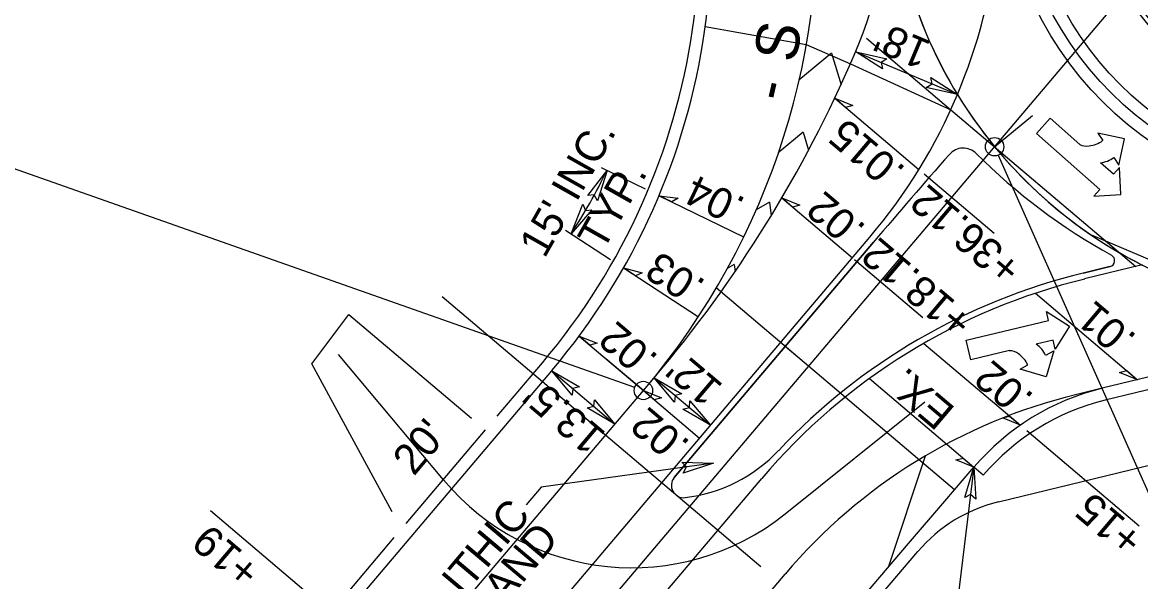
# Model space of a CAD drawing. Extents: x 1761082 to 1764358, y 421907 to 425434.
# Drawn here: x 1762006.6 to 1762189, y 422867.6 to 422958.8 of the extents above; entities that cross this region are included whole.
import ezdxf

# ---------------------------------------------------------------- set-up
doc = ezdxf.new("R2010")
doc.units = 0
for name, color, linetype in [('MARK DUAL LEFT TURN ARROWS CELL', 7, 'Continuous'), ('MARK HOOKS CENTER STRAIGHT LEFT TURN ARROW CELL', 7, 'Continuous'), ('MARK HOOKS STRAIGHT RIGHT TURN ARROW CELL', 7, 'Continuous'), ('MARK LEFT TURN ARROW CELL', 7, 'Continuous'), ('MARK ONLY WORD SYMBOL CELL', 7, 'Continuous'), ('MARK STRAIGHT RIGHT ARROW CELL', 7, 'Continuous'), ('MARK UTURN ARROW CELL', 7, 'Continuous'), ('Prop Conc Driveway', 7, 'Continuous'), ('Prop Horizontal Alignment Tick Large', 7, 'Continuous'), ('Prop Mkg 3ft Min Skp 3ft Wide White', 7, 'Continuous'), ('Prop Mkg 3ft Min Skp 9ft White', 7, 'Continuous'), ('Prop Mkg 3ft Min Skp 9ft Wide White', 7, 'Continuous'), ('Prop Mkg Min Skp 6ft Yellow', 7, 'Continuous'), ('Prop Mkg Skp Wht', 7, 'Continuous'), ('Prop Mkg Solid White Diagonals', 7, 'Continuous'), ('Prop Mkg Solid White Gore Line', 7, 'Continuous'), ('Prop Mkg Solid White Multiple Diagonals V8i', 7, 'Continuous'), ('Prop Mkg Solid Yel Skip LT', 7, 'Continuous'), ('Prop Mkg Solid Yel Skip RT', 7, 'Continuous'), ('Prop Mkg Solid Yellow Diagonals', 7, 'Continuous'), ('Prop Mkg Solid Yellow Edge Line', 7, 'Continuous'), ('Prop Mkg Solid Yellow Lane Line', 7, 'Continuous'), ('Prop Mkr CR 80ft Spc', 7, 'Continuous'), ('Prop Mkr Yel 80ft Spc', 7, 'Continuous'), ('Scratch_Level_0', 7, 'Continuous'), ('Scratch_Level_1', 7, 'Continuous'), ('Scratch_Level_5', 7, 'Continuous'), ('Text', 7, 'Continuous')]:
    doc.layers.add(name, color=color, linetype=linetype)

msp = doc.modelspace()

# ---------------------------------------------------------------- linework, layer by layer
at = {"layer": 'MARK DUAL LEFT TURN ARROWS CELL'}
msp.add_line((1762165.16, 422938.49), (1762188.21, 422918.96), dxfattribs=at)
at = {"layer": 'MARK HOOKS CENTER STRAIGHT LEFT TURN ARROW CELL'}
msp.add_line((1762134.83, 422902.69), (1762131.02, 422905.92), dxfattribs=at)
at = {"layer": 'MARK LEFT TURN ARROW CELL'}
for p, q in [((1762241.31, 422911.3), (1762183.21, 422897.16)), ((1762084.06, 422894.58), (1762091.42, 422903.27)), ((1762163.32, 422884.94), (1762161.8, 422886.24)), ((1762056.89, 422862.51), (1762067.26, 422874.75))]:
    msp.add_line(p, q, dxfattribs=at)
for centre, radius, start, end in [((1762009.01, 422973.08), 108, 319.7301, 23.7856), ((1762192.2, 422860.24), 38, 103.6821, 139.4555)]:
    msp.add_arc(centre, radius, start, end, dxfattribs=at)
at = {"layer": 'MARK ONLY WORD SYMBOL CELL'}
msp.add_line((1762069.2, 422877.04), (1762082.12, 422892.3), dxfattribs=at)
at = {"layer": 'MARK STRAIGHT RIGHT ARROW CELL'}
msp.add_line((1761294.53, 421910.78), (1762672.97, 423537.92), dxfattribs=at)
msp.add_arc((1762016.33, 422976.3), 120, 319.7301, 48.9609, dxfattribs=at)
at = {"layer": 'MARK UTURN ARROW CELL'}
for points in [[(1762106.48, 422899.23), (1761972.71, 422946.36), (1761882.86, 422840.3)], [(1762165.77, 422937.12), (1762234.28, 422783.03), (1762150.66, 422684.32)]]:
    msp.add_lwpolyline(points, dxfattribs=at)
for centre in [(1762165.16, 422938.49), (1762165.16, 422938.49), (1762107.89, 422898.74)]:
    msp.add_circle(centre, 1.5, dxfattribs=at)
at = {"layer": 'Prop Conc Driveway'}
for p, q in [((1762053.82, 422903.11), (1762059.86, 422911.16)), ((1762059.86, 422911.16), (1762079.83, 422894.23)), ((1762066.91, 422878.97), (1762053.82, 422903.11))]:
    msp.add_line(p, q, dxfattribs=at)
at = {"layer": 'Prop Horizontal Alignment Tick Large'}
for p, q in [((1762165.16, 422938.49), (1762171.34, 422943.57)), ((1762107.89, 422898.74), (1762101.79, 422903.91))]:
    msp.add_line(p, q, dxfattribs=at)
at = {"layer": 'Prop Mkg 3ft Min Skp 3ft Wide White'}
msp.add_line((1761294.53, 421910.78), (1762672.97, 423537.92), dxfattribs=at)
for centre, radius, start, end in [((1762016.33, 422976.3), 120, 319.7301, 48.9609), ((1762223.1, 422986.12), 75, 149.3002, 219.4239), ((1762223.1, 422986.12), 75, 219.4239, 320.8368)]:
    msp.add_arc(centre, radius, start, end, dxfattribs=at)
at = {"layer": 'Prop Mkg 3ft Min Skp 9ft White'}
msp.add_circle((1762223.1, 422986.12), 55, dxfattribs=at)
at = {"layer": 'Prop Mkg 3ft Min Skp 9ft Wide White'}
msp.add_line((1762165.78, 422880.57), (1762244.15, 422899.64), dxfattribs=at)
msp.add_lwpolyline([(1762074.01, 422782.47), (1762075.07, 422783.67), (1762078.74, 422787.78), (1762082.33, 422791.8), (1762088.47, 422798.73), (1762093.54, 422804.54), (1762099.47, 422811.3), (1762102.88, 422815.18), (1762106.42, 422819.2), (1762109.92, 422823.18), (1762113.38, 422827.1), (1762116.8, 422830.99), (1762122.94, 422837.96), (1762127.73, 422843.46), (1762131.92, 422848.3), (1762136.29, 422853.34), (1762141.13, 422858.95), (1762152.67, 422872.49)], dxfattribs=at)
msp.add_arc((1762171.7, 422856.28), 25, 103.6821, 139.5617, dxfattribs=at)
at = {"layer": 'Prop Mkg Skp Wht'}
for p, q in [((1762240.84, 422913.25), (1762182.73, 422899.1)), ((1762058.44, 422861.25), (1762092.94, 422901.97))]:
    msp.add_line(p, q, dxfattribs=at)
msp.add_lwpolyline([(1762072.51, 422783.8), (1762073.58, 422785), (1762077.25, 422789.11), (1762080.84, 422793.13), (1762086.97, 422800.06), (1762092.04, 422805.85), (1762097.97, 422812.62), (1762101.38, 422816.5), (1762104.92, 422820.52), (1762108.42, 422824.5), (1762111.88, 422828.43), (1762115.3, 422832.31), (1762121.43, 422839.28), (1762126.22, 422844.77), (1762130.41, 422849.61), (1762134.78, 422854.65), (1762139.61, 422860.25), (1762145.2, 422866.81), (1762151.14, 422873.79), (1762157.03, 422880.67), (1762161.8, 422886.24)], dxfattribs=at)
for centre, radius, start, end in [((1762009.01, 422973.08), 110, 319.7301, 23.7856), ((1762192.2, 422860.24), 40, 103.6821, 139.4555)]:
    msp.add_arc(centre, radius, start, end, dxfattribs=at)
at = {"layer": 'Prop Mkg Solid White Diagonals'}
for p, q in [((1762145.43, 422922.94), (1762112.92, 422884.56)), ((1762179.62, 422917.9), (1762183.98, 422918.96))]:
    msp.add_line(p, q, dxfattribs=at)
for radius in [53, 43]:
    msp.add_circle((1762223.1, 422986.12), radius, dxfattribs=at)
for centre, radius, start, end in [((1762908.44, 422276.55), 1000, 138.64649, 139.7301), ((1762160.05, 422935.27), 3, 45.1345, 138.6465), ((1762232.71, 423008.27), 100, 225.1345, 241.0035), ((1762183.75, 422919.93), 1, 283.6821, 61.0035), ((1762203.51, 422819.76), 101, 103.6821, 136.7449), ((1762111.74, 422906.1), 25, 276.7589, 316.7449), ((1762114.45, 422883.26), 2, 139.7301, 276.7589)]:
    msp.add_arc(centre, radius, start, end, dxfattribs=at)
at = {"layer": 'Prop Mkg Solid White Gore Line'}
for radius in [43, 42.25]:
    msp.add_circle((1762223.1, 422986.12), radius, dxfattribs=at)
at = {"layer": 'Prop Mkg Solid White Multiple Diagonals V8i'}
for p, q in [((1762142.51, 422954), (1762159.1, 422947.01)), ((1762134.83, 422902.69), (1762119.76, 422915.46)), ((1762127.03, 422869.98), (1762075.06, 422914.01)), ((1762075.31, 422884.17), (1762058.19, 422904.63)), ((1761636.39, 422342), (1762107.89, 422898.74)), ((1762131, 422878.62), (1762153.81, 422896.89))]:
    msp.add_line(p, q, dxfattribs=at)
for radius in [57, 53]:
    msp.add_circle((1762223.1, 422986.12), radius, dxfattribs=at)
for centre, radius, start, end in [((1762076.16, 422981.94), 90, 337.1611, 1.6276), ((1762223.1, 422986.12), 75, 181.6276, 211.4287), ((1762105.99, 422909.83), 40, 219.9102, 308.6979)]:
    msp.add_arc(centre, radius, start, end, dxfattribs=at)
at = {"layer": 'Prop Mkg Solid Yel Skip RT'}
for p, q in [((1762142.51, 422954), (1762159.1, 422947.01)), ((1762100.98, 422935.12), (1762108.2, 422931.61)), ((1762153.67, 422934.07), (1762165.11, 422924.38)), ((1762095.2, 422924.88), (1762102.55, 422920.08)), ((1762142.33, 422920.09), (1762153.47, 422910.65)), ((1762092.94, 422901.97), (1762103.22, 422893.27)), ((1762109.66, 422900.81), (1762118.81, 422893.06)), ((1762170.43, 422892.19), (1762188.74, 422876.68)), ((1762037.29, 422879.17), (1762057.99, 422861.63))]:
    msp.add_line(p, q, dxfattribs=at)
for points in [[(1762119.35, 422886.89), (1762091.23, 422882.99), (1762088.76, 422880.08)], [(1762161.8, 422886.24), (1762153.19, 422815.74), (1762150.72, 422812.83)]]:
    msp.add_lwpolyline(points, dxfattribs=at)
msp.add_arc((1762016.33, 422976.3), 95.22, 326.8921, 334.054, dxfattribs=at)
at = {"layer": 'Prop Mkg Solid Yellow Diagonals'}
for p, q in [((1762174.21, 422943.15), (1762172.02, 422940.68)), ((1762179.04, 422938.87), (1762174.21, 422943.15)), ((1762172.02, 422940.68), (1762182.35, 422931.53)), ((1762186.35, 422939.81), (1762182.01, 422940.72)), ((1762182.01, 422940.72), (1762182.79, 422939.49)), ((1762185.44, 422935.47), (1762186.35, 422939.81)), ((1762184.62, 422936.73), (1762185.44, 422935.47)), ((1762184.54, 422934), (1762182.41, 422935.89)), ((1762185.53, 422935.12), (1762184.54, 422934)), ((1762185.77, 422930.71), (1762185.53, 422935.12)), ((1762182.35, 422931.53), (1762181.36, 422930.41)), ((1762181.36, 422930.41), (1762185.77, 422930.71)), ((1762173.96, 422910.14), (1762173.61, 422911.6)), ((1762173.61, 422911.6), (1762177.36, 422909.25)), ((1762160.53, 422906.96), (1762173.96, 422910.14)), ((1762177.36, 422909.25), (1762175.07, 422905.47)), ((1762161.3, 422903.75), (1762160.53, 422906.96)), ((1762174.72, 422906.93), (1762171.95, 422906.28)), ((1762175.07, 422905.47), (1762174.72, 422906.93)), ((1762167.57, 422905.24), (1762161.3, 422903.75)), ((1762173.51, 422904.49), (1762174.82, 422905.21)), ((1762174.82, 422905.21), (1762173.57, 422900.96)), ((1762169.32, 422902.21), (1762170.59, 422902.92)), ((1762173.57, 422900.96), (1762169.32, 422902.21))]:
    msp.add_line(p, q, dxfattribs=at)
for centre, radius, start, end in [((1762180.18, 422941.12), 2.52, 243.0951, 279.4071), ((1762180.13, 422943.04), 4.43, 275.917, 306.7706), ((1762181.95, 422940.29), 4.43, 276.0108, 306.8894), ((1762169.47, 422902.61), 4.43, 24.9389, 55.8175), ((1762167.51, 422902.71), 2.52, 52.4212, 88.7332), ((1762166.57, 422901.04), 4.43, 25.0578, 55.9113)]:
    msp.add_arc(centre, radius, start, end, dxfattribs=at)
at = {"layer": 'Prop Mkg Solid Yellow Edge Line'}
msp.add_line((1762055.03, 422836.33), (1762107.89, 422898.74), dxfattribs=at)
at = {"layer": 'Prop Mkg Solid Yellow Lane Line'}
for points in [[(1762146.87, 422951.21), (1762142.51, 422954), (1762147.59, 422952.84), (1762146.64, 422952.26)], [(1762154.74, 422949.8), (1762159.1, 422947.01), (1762154.02, 422948.17), (1762154.97, 422948.75)], [(1762098.81, 422930.53), (1762101.96, 422934.64), (1762100.38, 422929.68), (1762099.88, 422930.67)], [(1762099.5, 422928.19), (1762096.1, 422924.29), (1762097.99, 422929.14), (1762098.43, 422928.12)], [(1762096.27, 422898), (1762092.94, 422901.97), (1762097.45, 422899.35), (1762096.36, 422899.08)], [(1762112.98, 422896.85), (1762109.66, 422900.81), (1762114.16, 422898.19), (1762113.07, 422897.92)], [(1762099.89, 422897.24), (1762103.22, 422893.27), (1762098.72, 422895.89), (1762099.8, 422896.17)], [(1762115.49, 422897.03), (1762118.81, 422893.06), (1762114.31, 422895.68), (1762115.39, 422895.95)], [(1762114.17, 422887.06), (1762119.35, 422886.89), (1762114.39, 422885.28), (1762114.91, 422886.27)], [(1762160.31, 422881.28), (1762161.8, 422886.24), (1762162.08, 422881.03), (1762161.26, 422881.79)]]:
    msp.add_lwpolyline(points, close=True, dxfattribs=at)
at = {"layer": 'Prop Mkr CR 80ft Spc'}
msp.add_line((1762158.63, 422882.53), (1762134.83, 422902.69), dxfattribs=at)
at = {"layer": 'Prop Mkr Yel 80ft Spc'}
for start, end in [(149.3002, 219.4239), (219.4239, 320.8368)]:
    msp.add_arc((1762223.1, 422986.12), 75, start, end, dxfattribs=at)
at = {"layer": 'Scratch_Level_0'}
for p, q in [((1762117.99, 422958.13), (1762134.46, 422955.18)), ((1762134.46, 422955.18), (1762141.66, 422952.02)), ((1762144.29, 422956.18), (1762158.02, 422944.54)), ((1762138.56, 422953.78), (1762133.26, 422949.33)), ((1762138.56, 422953.78), (1762140.12, 422948.6)), ((1762141.66, 422952.02), (1762158.02, 422944.54)), ((1762158.02, 422944.54), (1762188.21, 422918.96)), ((1762133.93, 422940.89), (1762129.88, 422937.49)), ((1762133.93, 422940.89), (1762134.82, 422937.92)), ((1762128.43, 422929.48), (1762126.26, 422928.18)), ((1762128.43, 422929.48), (1762128.73, 422927.25)), ((1762065.62, 422830.27), (1762144.83, 422923.77)), ((1762122.69, 422919.29), (1762121.56, 422918.62)), ((1762122.69, 422919.29), (1762122.85, 422918.13)), ((1762189.22, 422919.21), (1762179.85, 422916.93)), ((1762107.89, 422898.74), (1762109.66, 422900.81)), ((1762182.73, 422899.1), (1762178.38, 422898.04)), ((1762153.83, 422888.04), (1762147.81, 422869.87)), ((1762095.46, 422846.93), (1762127.21, 422884.4)), ((1762105.31, 422838.44), (1762131, 422868.77))]:
    msp.add_line(p, q, dxfattribs=at)
for centre, radius, start, end in [((1762016.33, 422976.3), 120, 319.7301, 48.9609), ((1762076.16, 422981.94), 72, 336.6875, 1.6276), ((1761949.42, 423036.56), 210, 319.7301, 336.6875), ((1762076.16, 422981.94), 90, 319.7301, 337.1611), ((1762223.1, 422986.12), 75, 211.4287, 243.1463), ((1762203.51, 422819.76), 100, 103.6821, 139.7301), ((1762199.67, 422810.6), 90, 103.6821, 139.7301)]:
    msp.add_arc(centre, radius, start, end, dxfattribs=at)
at = {"layer": 'Scratch_Level_1'}
msp.add_lwpolyline([(1762180.78, 422924.2), (1762313.18, 422868.04), (1762249.34, 422792.68)], dxfattribs=at)
at = {"layer": 'Scratch_Level_5'}
for p, q in [((1762139.1, 422946.42), (1762152.82, 422934.79)), ((1762110.44, 422930.51), (1762124.24, 422923.8)), ((1762130.46, 422930.14), (1762141.97, 422920.39)), ((1762104.64, 422918.72), (1762116.85, 422910.76)), ((1762171.82, 422914.61), (1762188.47, 422900.5)), ((1762097.41, 422907.61), (1762107.89, 422898.74)), ((1762153.62, 422906.43), (1762169.37, 422893.09)), ((1762144.75, 422900.68), (1762161.8, 422886.24)), ((1762107.89, 422898.74), (1762117.05, 422890.98))]:
    msp.add_line(p, q, dxfattribs=at)
for points in [[(1762139.1, 422946.42), (1762142.03, 422945.24), (1762140.86, 422944.92)], [(1762110.44, 422930.51), (1762113.58, 422930.1), (1762112.52, 422929.5)], [(1762130.46, 422930.14), (1762133.4, 422928.96), (1762132.23, 422928.65)], [(1762104.64, 422918.72), (1762107.7, 422917.92), (1762106.58, 422917.45)], [(1762097.41, 422907.61), (1762100.35, 422906.44), (1762099.18, 422906.12)], [(1762188.47, 422900.5), (1762185.54, 422901.67), (1762186.71, 422901.99)], [(1762107.89, 422898.74), (1762110.83, 422897.56), (1762109.66, 422897.24)], [(1762169.37, 422893.09), (1762166.44, 422894.26), (1762167.61, 422894.58)], [(1762161.8, 422886.24), (1762158.86, 422887.41), (1762160.03, 422887.73)]]:
    msp.add_lwpolyline(points, close=True, dxfattribs=at)
at = {"layer": 'Text'}
for p, q in [((1762112.92, 422884.56), (1762145.43, 422922.94)), ((1762183.98, 422918.96), (1762179.62, 422917.9))]:
    msp.add_line(p, q, dxfattribs=at)
for centre, radius, start, end in [((1762908.44, 422276.55), 1000, 138.64649, 139.7301), ((1762160.05, 422935.27), 3, 45.1345, 138.6465), ((1762232.71, 423008.27), 100, 225.1345, 241.0035), ((1762183.75, 422919.93), 1, 283.6821, 61.0035), ((1762203.51, 422819.76), 101, 103.6821, 136.7449), ((1762111.74, 422906.1), 25, 276.7589, 316.7449), ((1762114.45, 422883.26), 2, 139.7301, 276.7589)]:
    msp.add_arc(centre, radius, start, end, dxfattribs=at)

# ---------------------------------------------------------------- texts
at = {"layer": 'MARK HOOKS STRAIGHT RIGHT TURN ARROW CELL'}
for s, rotation, p in [('S', 80.2488, (1762132.73, 422952.04)), ('-', 77.0525, (1762131.24, 422945.59))]:
    msp.add_text(s, height=7, rotation=rotation, dxfattribs=at).set_placement(p)
at = {"layer": 'Prop Mkg Min Skp 6ft Yellow'}
for s, rotation, p in [('.015', 139.7301, (1762150.86, 422934.95)), ("15' INC.", 60.4731, (1762091.77, 422920.15)), ('TYP.', 60.4731, (1762101.31, 422921.35)), ('.04', 154.054, (1762124.78, 422929.96)), ('.02', 139.7301, (1762144.41, 422925.49)), ('.03', 146.8921, (1762118.28, 422916.51)), ('.01', 139.7301, (1762188.54, 422907.6)), ('.02', 139.7301, (1762110.54, 422904.28)), ('EX.', 139.7301, (1762158.95, 422895.79)), ('.02', 139.7301, (1762171.78, 422897.92)), ('.02', 139.7301, (1762115.72, 422890.28))]:
    msp.add_text(s, height=5, rotation=rotation, dxfattribs=at).set_placement(p)
at = {"layer": 'Prop Mkg Solid Yel Skip LT'}
for s, rotation, p in [("18'", 157.1611, (1762155.06, 422955.57)), ('+36.12', 139.7301, (1762169.97, 422919.28)), ('+18.12', 139.7301, (1762162, 422910.61)), ("12'", 139.7301, (1762121.1, 422899.56)), ("13.5'", 139.7301, (1762102, 422891.71)), ("20'", 49.8262, (1762070.45, 422884.65)), ('MONOLITHIC', 49.892, (1762062.64, 422846.22)), ('+15', 139.7301, (1762189.79, 422875.06)), ('+19', 139.7301, (1762045.78, 422869.86)), ('CONC. ISLAND', 49.892, (1762063.68, 422838.14))]:
    msp.add_text(s, height=5, rotation=rotation, dxfattribs=at).set_placement(p)

doc.saveas('drawing.dxf')
